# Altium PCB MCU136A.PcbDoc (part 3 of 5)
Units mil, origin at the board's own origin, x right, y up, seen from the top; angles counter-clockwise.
Board outline 3937.01 x 4724.41 mil, 4 copper layers (Top Layer, Signal Layer 1, Signal Layer 2, Bottom Layer), stack 60 mil thick; 390 components, 224 nets, 1130 pads, 1344 vias.
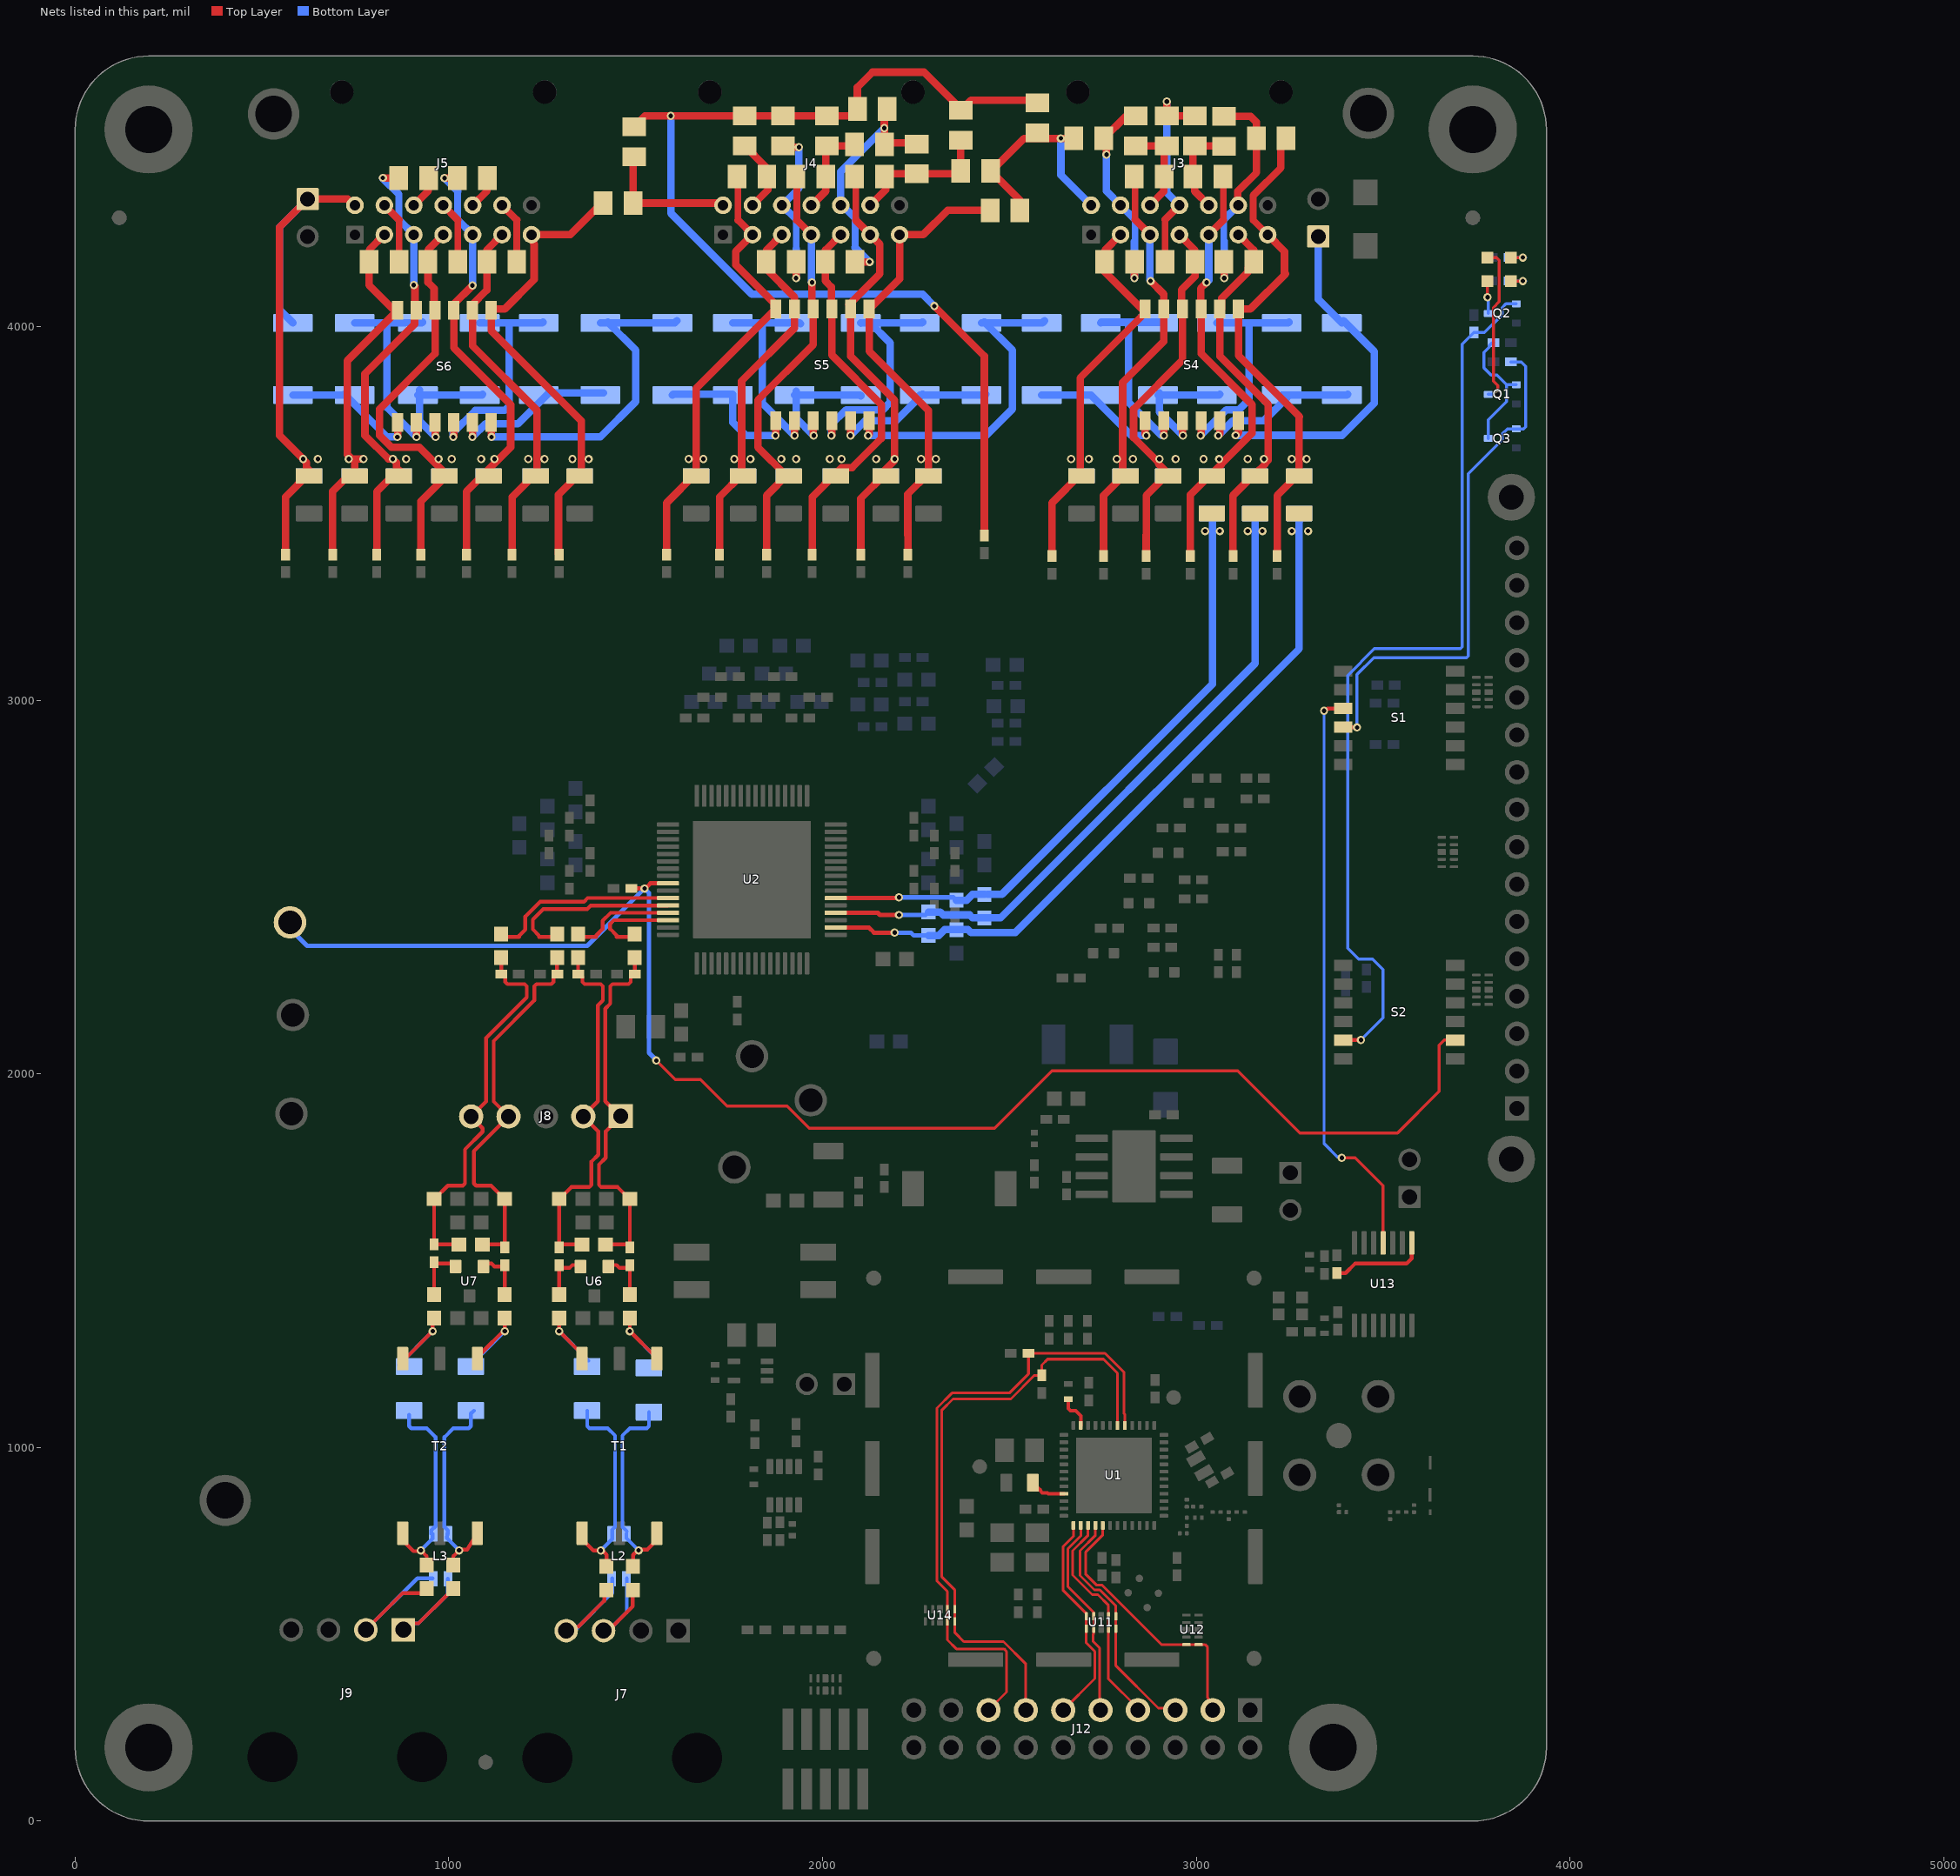
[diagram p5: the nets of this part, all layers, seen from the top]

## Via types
v1: diameter 22, hole 12, Top Layer to Bottom Layer, tented both sides, 890 vias
v2: diameter 22.01, hole 12.01, Top Layer to Bottom Layer, tented both sides, 402 vias
v3: diameter 19.68, hole 7.87, Top Layer to Bottom Layer, tented both sides, 21 vias
v4: diameter 24, hole 8, Top Layer to Bottom Layer, tented both sides, 12 vias
v5: diameter 20, hole 10, Top Layer to Bottom Layer, tented both sides, 7 vias
v6: diameter 24.8, hole 12.99, Top Layer to Bottom Layer, tented bottom, 6 vias
v7: diameter 17.46, hole 7.87, Top Layer to Bottom Layer, tented both sides, 6 vias

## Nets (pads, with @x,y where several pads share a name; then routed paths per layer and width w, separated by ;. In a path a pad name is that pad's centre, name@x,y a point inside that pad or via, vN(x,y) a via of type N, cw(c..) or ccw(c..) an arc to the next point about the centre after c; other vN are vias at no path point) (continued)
CB16: C21.2 C23.1 R34.2 R36.2 U2.6 | length 1683.6
  Top Layer w11.81: U2.6@2035.43,2470.47 2200,2470.47 2201.97,2472.44 v2(2204.72,2472.44) v2@2202.77,2470.49
  Bottom Layer w11.81: v2(2204.72,2472.44) 2350.39,2472.44 C23.1@2358.27,2464.57
  Bottom Layer w20: C23.1@2358.27,2464.57 2385.83,2464.57 2401.57,2480.31 C21.2@2433.07,2480.31 ; C21.2@2440.94,2480.31 2480.32,2480.31 3043.31,3043.31 R36.2@3043.31,3480.32
  other v2: 3023.62,3452.76 3062.99,3452.76
CB17: C19.2 C21.1 R31.2 R33.2 U2.4 | length 1813.8
  Top Layer w11.81: U2.4@2035.43,2431.1 2147.64,2431.1 2153.54,2425.2 v2(2204.72,2425.2)
  Bottom Layer w11.81: v2(2204.72,2425.2) 2275.59,2425.2 C19.2@2283.46,2433.07
  Bottom Layer w20: C19.2@2283.46,2433.07 2314.96,2433.07 2322.83,2425.2 2393.7,2425.2 2401.57,2417.32 C21.1@2433.07,2417.32 2476.38,2417.32 3157.81,3098.75 R33.2@3157.81,3495.67
  other v2: 3137.8,3452.76 3177.17,3452.76
CB18: C18.2 C19.1 R28.2 R30.2 U2.2 | length 1927.3
  Top Layer w11.81: U2.2@2035.43,2391.73 2124.02,2391.73 2137.8,2377.95 v2(2193.14,2377.95)
  Bottom Layer w11.81: v2(2193.14,2377.95) 2236.22,2377.95 2244.09,2370.08 C19.1@2283.46,2370.08
  Bottom Layer w20: C19.1@2283.46,2370.08 2311.02,2370.08 2326.77,2385.83 C18.2@2358.27,2385.83 2389.76,2385.83 2397.64,2377.95 2515.75,2377.95 3275.59,3137.8 3275.59,3480.32 R30.2@3283.46,3488.19
  other v2: 3255.91,3452.76 3299.21,3452.76
CC_EXT_IO: J12.3 U1.41 U12.1 U12.10 | length 730.9
  Top Layer w7: U1.41@2750,791.34 2750,765.75 2704.72,720.47 2704.72,659.79 2732.66,631.86 2747.43,631.86 2906.85,472.44 U12.10@2973.56,472.44 U12.1@3006.44,472.44 3023.62,472.44 3030.45,465.61 3030.45,418.37 3030.45,329.93 3033,327.38 3033,307.94 J12.3@3044.09,296.85
CC_I2C_SCL: J12.13 R157.1 U1.18 U14.5 U14.6 | length 1656.7
  Top Layer w7: J12.13@2544.09,296.85 2543.31,297.64 2543.31,421.51 2484.5,480.32 2377.95,480.32 2354.33,503.94 2354.33,534.18 2354.33,567.06 2354.33,618.11 2319.24,653.2 2319.24,1100.07 2349.09,1129.92 2503.94,1129.92 2566.93,1192.91 R157.1@2586.61,1192.91 2586.61,1220.47 2602.36,1236.22 2610.24,1236.22 2751.97,1236.22 2789.37,1198.82 U1.18@2789.37,1059.06
CC_I2C_SDA: J12.15 R156.1 U1.17 U14.4 U14.7 | length 1734.5
  Top Layer w7: U14.4@2333.85,534.18 2333.85,566.95 U14.7@2334.18,567.28 ; U14.4@2334.18,534.18 2334.18,484.71 2358.2,460.69 2469.74,460.69 2485.74,460.69 2492.45,453.99 2492.45,345.2 J12.15@2444.09,296.85 ; U14.7@2334.18,567.06 2334.18,614.63 2306.24,642.58 2306.24,1105.45 2346.46,1145.67 2500,1145.67 2551.18,1196.85 R156.1@2551.18,1248.03 ; R156.1@2551.18,1251.97 2755.91,1251.97 2807.09,1200.79 2807.09,1090.55 2809.06,1088.58 U1.17@2809.06,1059.06
CC_SPI_CS: J12.11 U1.37 U11.1 U11.10 | length 576.3
  Top Layer w7: J12.11@2644.09,296.85 2728.45,381.2 2728.45,453.99 2705.85,476.59 2705.85,515.06 2705.85,547.93 2705.85,555.56 2643.29,618.11 2643.29,733.99 2671.26,761.96 U1.37@2671.26,791.34
CC_SPI_MISO: J12.7 U1.39 U11.4 U11.7 | length 585.3
  Top Layer w7: U1.39@2710.63,791.34 2710.63,764.56 2669.29,723.22 2669.29,658.46 2721.89,605.86 2736.66,605.86 2765.34,577.18 U11.7@2765.34,547.93 ; U11.4@2764.9,515.06 U11.7@2764.9,547.5 ; U11.4@2765.34,515.06 2765.34,380.33 J12.7@2842.52,303.15
CC_SPI_MOSI: J12.9 U1.38 U11.2 U11.9 | length 546.6
  Top Layer w7: U1.38@2690.94,791.34 2690.94,763.26 2656.29,728.61 2656.29,627.17 2725.53,557.93 2725.53,547.93 2725.97,547.5 2725.97,515.5 2725.53,515.06 2725.53,500.9 2724.34,499.7 2724.34,480.39 2741.45,463.28 2741.45,299.5 J12.9@2744.09,296.85
CC_SPI_SCK: J12.5 U1.40 U11.5 U11.6 | length 649.5
  Top Layer w7: U1.40@2730.32,791.34 2730.32,764.56 2688.98,723.22 2688.98,657.16 2727.27,618.86 2742.04,618.86 2785.02,575.88 U11.6@2785.02,547.93 U11.5@2785.02,515.06 2785.02,415.76 2898.78,302.01 2938.94,302.01 J12.5@2944.09,296.85
CELL0: J5.2 J6.1 R106.1 R107.1 R108.1 R176.1 | length 1574.7
  Top Layer w20: R107.1@562.99,3385.83 R107.1@562.99,3389.76 562.99,3544.09 R106.1@625.98,3607.09 ; R106.1@649.61,3606.3 635.74,3606.3 619.37,3622.68 619.37,3636 610.24,3645.13 v2(610.24,3645.67) 547.24,3708.66 547.24,4266.54 J6.1@622.05,4341.34 729.53,4341.34 J5.2@748.03,4322.83
  Bottom Layer w20: R176.1@582.68,4009.84 547.24,4045.28 547.24,4266.54 J6.1@622.05,4341.34
  other v2: 649.61,3645.67
CELL1: J5.3 R101.1 R103.1 R104.1 R111.2 S6.12 | length 1007.2
  Top Layer w20: R103.1@688.98,3389.76 688.98,3559.06 721.42,3591.5 721.61,3591.5 728.53,3598.41 R101.1@728.53,3598.61 ; R101.1@748.03,3607.09 748.03,3645.67 ; v2(771.65,3645.67) 748.03,3645.67 ; R111.2@786.77,4173.23 786.77,4110.87 S6.12@858.27,4039.37 ; R111.2@787.4,4173.23 787.4,4205.94 J5.3@827.52,4246.06 ; S6.12@863.19,4043.7 728.35,3908.86 728.35,3657.39 740.06,3645.67 748.03,3645.67
  other v1: 732.28,3645.67
CELL1_Lad: R175.1 R176.2 S6.1 | length 366.2
  Top Layer w20: v1(862.2,3704.72) 863.19,3705.71 S6.1@863.19,3743.7
  Bottom Layer w20: R176.2@582.68,3816.93 R175.1@720.47,3816.93 ; R175.1@720.47,3818.9 834.65,3704.72 v1(862.2,3704.72)
CELL2: J5.5 R97.1 R98.1 R99.1 R110.2 S6.11 | length 1216.4
  Top Layer w10: v1(823.59,4398.26) v1@824.2,4397.64
  Top Layer w20: R98.1@807.09,3389.76 807.09,3558.36 839.72,3591 839.72,3591.5 855.32,3607.09 R97.1@866.14,3607.09 ; v1@824.2,4397.64 R110.2@865.51,4397.64 ; R97.1@871.65,3612.6 869.6,3612.6 859.52,3622.68 859.52,3636 850.39,3645.13 v2(850.39,3645.67) 850.01,3646.05 838.2,3646.05 775.59,3708.66 775.59,3874.02 908.19,4006.61 908.19,4038.7 S6.11@913.19,4043.7 ; v1(906.13,4111.17) 909.45,4107.85 S6.11@909.45,4043.7
  Bottom Layer w18: 866.14,4286.18 866.14,4354.33
  Bottom Layer w20: v1@822.83,4397.64 866.14,4354.33 ; 866.14,4286.18 J5.5@906.26,4246.06 v1@906.26,4110.98
  other v2: 885.83,3645.67
CELL2_Lad: R174.1 R175.2 S6.2 | length 556.7
  Top Layer w20: S6.2@913.19,3743.7 913.19,3704.92 v1(913.39,3704.72)
  Bottom Layer w20: R175.2@748.03,4009.84 R174.1@917.32,4009.84 927.16,4009.84 R174.1@929.13,4011.81 ; 834.65,4007.87 834.65,3783.46 v1(913.39,3704.72)
CELL2_NEG: J5.4 R111.1 | length 167.8
  Top Layer w18: R111.1@866.77,4173.23 866.77,4285.55
  Top Layer w20: J5.4@827.52,4324.8 866.77,4285.55
CELL3: J5.7 R94.1 R95.1 R96.1 R109.2 S6.10 | length 1099
  Top Layer w20: R95.1@925.2,3385.83 925.2,3532.28 989.76,3596.85 995.67,3602.76 921.26,3677.17 846.46,3677.17 814.96,3708.66 814.96,3779.53 963.19,3927.76 S6.10@963.19,4043.7 ; R109.2@944.25,4173.23 944.25,4118.74 960.63,4102.36 S6.10@960.63,4043.7 ; R109.2@944.88,4173.23 944.88,4205.94 J5.7@985,4246.06 ; R94.1@983.86,3602.76 R94.1@988.19,3607.09
  other v2: 972.44,3645.67 1007.87,3645.67
CELL3_Lad: R173.1 R174.2 S6.3 | length 357.5
  Top Layer w20: S6.3@963.19,3743.7 963.19,3706.1 v1(964.57,3704.72)
  Bottom Layer w20: R174.2@917.32,3816.93 1088.58,3816.93 R173.1@1090.55,3818.9 ; R174.2@921.26,3830.71 921.26,3748.03 v1(964.57,3704.72)
CELL3_NEG: J5.6 R110.1 | length 100.6
  Top Layer w20: J5.6@906.26,4324.8 944.88,4363.43 R110.1@944.88,4409.45
CELL4: J5.9 R91.1 R92.1 R93.1 R105.2 S6.9 | length 1203.5
  Top Layer w20: v1(988.19,4397.64) R105.2@1019.68,4397.64 ; S6.9@1011.81,4043.7 1011.81,4058.72 v1(1063.37,4110.28) ; S6.9@1013.19,4043.7 1013.19,3943.5 1165.35,3791.34 1165.35,3677.17 R93.1@1100.79,3612.6 ; R92.1@1047.24,3393.7 1047.24,3558.86 1079.88,3591.5 1095.47,3607.09 R93.1@1106.3,3607.09
  Bottom Layer w10: v1@1062.99,4110.24 v1@1063.74,4110.98
  Bottom Layer w18: 1023.62,4286.18 1023.62,4362.2
  Bottom Layer w20: v1(988.19,4397.64) 1023.62,4362.2 ; 1023.62,4286.18 J5.9@1063.74,4246.06 v1@1063.74,4110.98
  other v1: 1122.05,3645.67
  other v2: 1086.61,3645.67
CELL4_Lad: R172.1 R173.2 S6.4 | length 617
  Top Layer w20: v1(1011.81,3704.72) 1013.19,3706.1 S6.4@1013.19,3743.7
  Bottom Layer w20: v1(1011.81,3704.72) 1011.81,3716.54 1070.87,3775.59 1149.7,3775.59 1161.42,3787.31 1161.42,4003.94 ; R173.2@1082.68,4009.84 R172.1@1240.16,4009.84 1250,4009.84 R172.1@1251.97,4011.81
CELL4_NEG: J5.8 R109.1 | length 167.8
  Top Layer w18: R109.1@1024.25,4173.23 1024.25,4285.55
  Top Layer w20: J5.8@985,4324.8 1024.25,4285.55
CELL5: J5.11 R86.1 R88.1 R89.1 R102.2 S6.8 | length 964.9
  Top Layer w20: S6.8@1062.99,4059.06 1101.73,4097.8 R102.2@1101.73,4173.23 ; S6.8@1063.19,4043.7 1063.19,3948.62 1236,3775.81 1236,3610.8 1169.29,3544.09 R88.1@1169.29,3397.64 ; R102.2@1102.36,4173.23 1102.36,4205.94 J5.11@1142.48,4246.06
  other v1: 1255.91,3645.67
  other v2: 1212.6,3645.67
CELL5_Lad: R171.1 R172.2 S6.5 | length 438.4
  Top Layer w20: v1(1062.99,3704.72) 1063.19,3704.92 S6.5@1063.19,3743.7
  Bottom Layer w20: v1(1062.99,3704.72) 1098.43,3740.16 1185.04,3740.16 1267.72,3822.83 R171.1@1413.39,3822.83
CELL5_NEG: J5.10 R105.1 | length 92.8
  Top Layer w20: J5.10@1063.74,4324.8 1102.36,4363.43 R105.1@1102.36,4401.57
CELL6: J5.13 R81.1 R82.1 R83.1 R100.2 S6.7 | length 1278.2
  Top Layer w20: S6.7@1113.19,4043.7 1113.19,3989.17 1354.33,3748.03 ; S6.7@1114.17,4047.24 1149.61,4047.24 1228.35,4125.98 1228.35,4220.73 1226.43,4222.64 1226.43,4240.85 J5.13@1221.22,4246.06 1324.8,4246.06 R100.2@1413.39,4334.65 ; R82.1@1295.28,3389.76 1293.46,3391.57 1293.46,3550.16 1354.74,3611.43 1354.74,3747.63
  other v1: 1374.14,3645.37
  other v2: 1330.71,3645.67
CELL6_Lad: R170.1 R171.2 S6.6 | length 915.1
  Top Layer w20: S6.6@1113.19,3743.7 1113.19,3705.71 v1(1114.17,3704.72)
  Bottom Layer w20: v1(1114.17,3704.72) 1405.51,3704.72 1500,3799.21 1500,3937.01 R171.2@1425.2,4011.81 ; R171.2@1405.51,4009.84 R170.1@1598.43,4009.84 1604.33,4009.84 R170.1@1610.24,4015.75
CELL6_NEG: J5.12 R102.1 | length 167.8
  Top Layer w18: R102.1@1181.73,4173.23 1181.73,4285.55
  Top Layer w20: J5.12@1142.48,4324.8 1181.73,4285.55
CELL7: J4.3 R74.1 R77.1 R78.1 R90.2 S5.12 | length 1212.9
  Top Layer w18: R90.2@1771.02,4401.57 1773.9,4398.7 1773.9,4285.16
  Top Layer w20: R77.1@1582.68,3389.76 1582.68,3528.35 1661.42,3607.09 1661.42,3834.06 S5.12@1875,4047.64 1870,4052.64 1870,4063.07 1767.72,4165.35 1767.72,4201.26 J4.3@1812.52,4246.06 ; 1773.9,4285.16 J4.3@1812.76,4246.3
  other v1: 1681.1,3645.67
  other v2: 1641.73,3645.67
CELL7_Lad: R169.1 R170.2 S5.1 | length 403.3
  Top Layer w20: v1(1874.02,3708.66) 1875,3709.65 S5.1@1875,3747.64
  Bottom Layer w20: R170.2@1598.43,3816.93 1600.39,3818.9 R169.1@1759.84,3818.9 ; R169.1@1759.84,3816.93 1759.84,3744.09 1795.28,3708.66 v1(1874.02,3708.66)
CELL7_NEG: J4.2 R100.1 R118.2 | length 371.3
  Top Layer w20: R118.2@1492.13,4456.69 1492.76,4456.06 R100.1@1492.76,4330.71 1732.28,4330.71 J4.2@1736.22,4326.77
CELL8: J4.5 R69.1 R70.1 R71.1 R87.2 S5.11 | length 984.3
  Top Layer w20: R70.1@1724.41,3397.64 1724.41,3544.09 R69.1@1785.04,3604.72 ; R69.1@1787.4,3607.09 R69.1@1785.04,3604.72 ; R87.2@1849.76,4173.23 1849.76,4154.17 1925.2,4078.74 S5.11@1925.2,4047.64 ; R87.2@1850.39,4173.23 1850.39,4205.2 J4.5@1891.26,4246.06 ; S5.11@1925,4047.64 1925,3995.87 1783.46,3854.33 1783.46,3606.3 R69.1@1785.04,3604.72
  other v1: 1763.78,3645.67
  other v2: 1807.09,3645.67
CELL8_Lad: R168.1 R169.2 S5.2 | length 552.1
  Top Layer w20: S5.2@1925,3747.64 1925,3708.86 v1(1925.2,3708.66)
  Bottom Layer w20: R169.2@1759.84,4009.84 R168.1@1925.2,4009.84 1938.98,4009.84 R168.1@1940.94,4007.87 ; 1838.58,4003.94 1838.58,3795.28 v1(1925.2,3708.66)
CELL8_NEG: J4.4 R90.1 R117.2 | length 207.1
  Top Layer w20: R117.2@1787.4,4488.19 1851.02,4424.57 R90.1@1851.02,4401.57 ; J4.4@1812.52,4324.8 1854.33,4366.61 R90.1@1854.33,4401.57
CELL9: J4.7 R65.1 R67.1 R68.1 R85.2 S5.10 | length 1146.8
  Top Layer w18: R85.2@1928.5,4401.57 1931.38,4398.7 1931.38,4285.16
  Top Layer w20: R67.1@1850.39,3389.76 1850.39,3548.03 R65.1@1909.45,3607.09 ; R65.1@1905.51,3598.43 1903.15,3600.79 1826.77,3677.17 1826.77,3803.15 1975,3951.38 S5.10@1975,4047.64 ; 1931.38,4285.16 J4.7@1968.5,4248.03 ; S5.10@1971.86,4055.7 v1(1971.86,4118.44)
  Bottom Layer w20: J4.7@1970,4246.06 1970,4120.55 v1@1972.44,4118.11
  other v2: 1889.76,3645.67 1929.13,3645.67
CELL9_Lad: R167.1 R168.2 S5.3 | length 355.2
  Top Layer w20: S5.3@1975,3747.64 1975,3710.04 v1(1976.38,3708.66)
  Bottom Layer w20: R168.2@1925.2,3816.93 2100.39,3816.93 R167.1@2102.36,3814.96 ; R168.2@1929.13,3826.77 1929.13,3755.91 v1(1976.38,3708.66)
CELL9_NEG: J4.6 R87.1 R116.2 | length 476.5
  Top Layer w20: R116.2@1889.76,4480.32 v1(1937.01,4480.32) ; v1(1929.13,4129.92) 1929.45,4130.24 1929.45,4172.91 R87.1@1929.76,4173.23
  Bottom Layer w18: 1929.13,4208.66 1929.88,4209.41 1929.88,4286.18
  Bottom Layer w20: v1(1929.13,4129.92) 1929.13,4208.66 ; 1929.88,4286.18 J4.6@1891.26,4324.8 1891.5,4325.04 1937.01,4370.55 v1(1937.01,4480.32)
CELL10: J4.9 R62.1 R63.1 R64.1 R80.2 S5.9 | length 1020.7
  Top Layer w20: R63.1@1972.44,3389.76 1972.44,3544.09 2035.43,3607.09 2051.02,3622.68 2079.37,3622.68 2157.48,3700.79 2157.48,3791.34 2025,3923.82 S5.9@2025,4047.64 ; R80.2@2007.24,4173.23 2007.24,4122.68 2023.62,4106.3 S5.9@2023.62,4055.12 ; R80.2@2007.87,4173.23 2007.87,4205.2 J4.9@2048.74,4246.06
  other v2: 2019.68,3645.67 2051.18,3645.67
CELL10_Lad: R166.1 R167.2 S5.4 | length 658.5
  Top Layer w20: v1(2023.62,3708.66) 2025,3710.04 S5.4@2025,3747.64
  Bottom Layer w10: R167.2@2102.36,4003.94 R167.2@2105.31,4006.89
  Bottom Layer w20: v1(2023.62,3708.66) 2023.62,3737.94 2062.99,3777.31 2161.03,3777.31 2181.1,3797.38 2181.1,3956.69 R167.2@2125.98,4011.81 ; R167.2@2102.36,4009.84 R166.1@2259.84,4009.84 2265.75,4009.84 R166.1@2267.72,4011.81
CELL10_NEG: J4.8 R84.2 R85.1 R115.2 | length 250.8
  Top Layer w20: J4.8@1972.44,4326.77 2008.5,4362.83 R85.1@2008.5,4401.57 R115.2@2008.5,4483.62 ; R115.2@2011.81,4483.62 2089.92,4483.62 R84.2@2090.55,4484.25
CELL11: J4.11 R55.1 R58.1 R59.1 R76.2 S5.8 | length 1144.7
  Top Layer w18: R76.2@2085.98,4401.57 2088.86,4398.7 2088.86,4284.68
  Top Layer w20: S5.8@2070.87,4059.06 2152.98,4141.17 2152.98,4220.56 J4.11@2127.48,4246.06 2088.86,4284.68 ; S5.8@2075,4047.64 2075,3921.06 2192.91,3803.15 2192.91,3641.73 R55.1@2161.42,3610.24 ; R58.1@2102.36,3393.7 2102.36,3540.16 R55.1@2169.29,3607.09
  other v1: 2192.91,3645.67
  other v2: 2143.55,3645.67
CELL11_Lad: R165.1 R166.2 S5.5 | length 455.6
  Top Layer w20: v1(2074.8,3708.66) 2075,3708.86 S5.5@2075,3747.64
  Bottom Layer w20: v1(2074.8,3708.66) 2114.17,3748.03 2196.85,3748.03 R166.2@2267.72,3818.9 ; R166.2@2259.84,3816.93 R165.1@2425.2,3816.93 2435.04,3816.93 R165.1@2437.01,3818.9
CELL11_NEG: J4.10 R79.2 R80.1 R84.1 R114.2 | length 668.6
  Top Layer w20: R80.1@2087.24,4173.23 v1(2125.98,4173.23) ; R114.2@2165.35,4582.68 v1(2165.35,4531.5) 2165.98,4530.87 R84.1@2165.98,4488.19 2169.92,4492.13 R79.2@2259.84,4492.13
  Bottom Layer w18: 2087.24,4211.97 2087.24,4229.95 2087.36,4230.07 2087.36,4262.06 2087.24,4262.18 2087.24,4290.71
  Bottom Layer w20: J4.10@2048.74,4324.8 2048.74,4414.88 v1(2165.35,4531.5) ; J4.10@2051.18,4326.77 2087.24,4290.71 ; 2087.24,4211.97 v1(2125.98,4173.23)
CELL12: J4.13 R50.1 R51.1 R52.1 R73.2 S5.7 | length 1244.3
  Top Layer w20: S5.7@2125,4047.64 2125,3934.06 2283.46,3775.59 R50.1@2283.46,3606.3 ; S5.7@2125.98,4047.24 2206.22,4127.48 J4.13@2206.22,4246.06 2269.68,4246.06 2334.65,4311.02 R73.2@2448.19,4311.02 ; R51.1@2228.35,3393.7 2228.35,3441.69 2228.09,3441.94 2228.09,3551.72 R50.1@2283.46,3607.09
  other v2: 2263.78,3645.67 2303.15,3645.67
CELL12_Lad: R164.1 R165.2 S5.6 | length 890.4
  Top Layer w20: v1(2122.05,3708.66) 2125,3711.61 S5.6@2125,3747.64
  Bottom Layer w20: v1(2122.05,3708.66) 2437.01,3708.66 2507.87,3779.53 2507.87,3937.01 R165.2@2433.07,4011.81 ; R165.2@2425.2,4009.84 R164.1@2586.6,4009.84 2588.58,4009.84 R164.1@2594.49,4015.75
CELL12_NEG: J4.12 R75.2 R76.1 R79.1 R113.2 | length 370.4
  Top Layer w20: J4.12@2127.48,4324.8 2169.29,4366.61 R76.1@2169.29,4401.57 ; R76.1@2165.98,4401.57 2173.23,4408.82 R79.1@2251.97,4408.82 R75.2@2357.64,4408.82 ; R75.2@2369.45,4417.32 2369.45,4498.1 R113.2@2370.08,4498.73
CELL13: J3.3 R43.1 R46.1 R47.1 R61.2 S4.12 | length 1027
  Top Layer w20: R46.1@2614.17,3389.76 2614.17,3528.35 2692.91,3607.09 2689.35,3610.65 2689.35,3862.58 2858.19,4031.42 2858.19,4042.64 S4.12@2863.19,4047.64 ; R61.2@2755.28,4173.23 2755.28,4146.3 S4.12@2858.56,4043.01 ; R61.2@2755.91,4173.23 2755.91,4204.45 J3.3@2797.52,4246.06
  other v2: 2665.35,3645.67 2712.6,3645.67
CELL13_Lad: R163.1 R164.2 S4.1 | length 364.6
  Top Layer w20: S4.1@2863.19,3747.64 2863.19,3711.61 v1(2866.14,3708.66)
  Bottom Layer w20: R164.2@2586.6,3816.93 2718.5,3816.93 2826.77,3708.66 v1(2866.14,3708.66)
CELL13_NEG: J3.2 R72.2 R73.1 R75.1 R112.2 | length 607.7
  Top Layer w20: R75.1@2449.45,4417.32 2527.56,4339.21 R73.1@2527.56,4307.09 ; R75.1@2452.76,4417.32 2539.37,4503.94 v1(2637.8,4503.94) R72.2@2669.29,4503.94
  Bottom Layer w20: v1(2637.8,4503.94) 2637.8,4405.79 J3.2@2718.78,4324.8
CELL14: J3.5 R40.1 R41.1 R42.1 R57.1 S4.11 | length 1121.9
  Top Layer w18: R57.1@2834.02,4401.57 2836.14,4399.45 2836.14,4286.18
  Top Layer w20: R41.1@2751.97,3385.83 2751.97,3548.03 2811.02,3607.09 2803.15,3614.96 2803.15,3850.5 2913.19,3960.54 S4.11@2913.19,4047.64 ; 2836.14,4286.18 J3.5@2876.26,4246.06 ; v1(2877.95,4122.05) 2913.39,4086.61 S4.11@2913.39,4047.64
  Bottom Layer w20: J3.5@2876.26,4246.06 2876.26,4123.74 v1(2877.95,4122.05)
  other v2: 2787.4,3645.67 2830.71,3645.67
CELL14_Lad: R162.1 R163.2 S4.2 | length 539.1
  Top Layer w20: S4.2@2913.19,3747.64 2913.19,3708.86 v1(2913.39,3708.66)
  Bottom Layer w20: R163.2@2744.09,4009.84 2746.06,4011.81 R162.1@2905.51,4011.81 ; 2818.9,4003.94 2818.9,3797.38 2907.61,3708.66 v1(2913.39,3708.66)
CELL14_NEG: J3.4 R60.2 R61.1 R72.1 | length 528.5
  Top Layer w20: R72.1@2752.6,4503.94 2811.65,4562.99 R60.2@2842.52,4562.99 ; v1(2759.84,4460.63) R72.1@2759.84,4484.25 ; v1(2834.65,4129.92) R61.1@2834.65,4157.48
  Bottom Layer w18: 2834.65,4227.07 2836.14,4228.57 2836.14,4286.18
  Bottom Layer w20: v1(2759.84,4460.63) 2759.84,4362.48 J3.4@2797.52,4324.8 2836.14,4286.18 ; v1(2834.65,4129.92) 2834.65,4227.07
CELL15: J3.7 R37.1 R38.1 R39.1 R54.1 S4.10 | length 1014
  Top Layer w20: R38.1@2866.14,3385.83 2866.14,3441.69 2866.39,3441.94 2866.39,3548.28 R37.1@2925.2,3607.09 ; R37.1@2929.13,3606.3 2925.39,3606.3 2898.78,3632.91 2898.78,3636.65 2832.19,3703.24 2832.19,3779.27 2963.19,3910.27 S4.10@2963.19,4047.64 ; J3.7@2955,4246.06 2996.06,4205 R54.1@2996.06,4173.23 ; S4.10@2960.63,4047.64 2960.63,4098.43 2996.69,4134.49 R54.1@2996.69,4173.23
  other v1: 2901.57,3645.67
  other v2: 2944.88,3645.67
CELL15_Lad: R161.1 R162.2 S4.3 | length 346
  Top Layer w20: S4.3@2963.19,3747.64 2963.19,3710.04 v1(2964.57,3708.66)
  Bottom Layer w20: R162.2@2897.64,3816.93 R161.1@3055.12,3816.93 3061.02,3816.93 R161.1@3062.99,3818.9 ; R162.2@2901.57,3822.83 2901.57,3771.65 v1(2964.57,3708.66)
CELL15_NEG: J3.6 R56.2 R57.2 R60.1 | length 259.9
  Top Layer w20: R60.1@2838.58,4483.62 R56.2@2916.69,4483.62 ; J3.6@2876.26,4324.8 2913.39,4361.93 R57.2@2913.39,4401.57 ; R57.2@2914.02,4401.57 2914.02,4480.94 R56.2@2916.69,4483.62 ; R56.2@2921.26,4488.19 R56.2@2916.69,4483.62
CELL16: J3.9 R34.1 R35.1 R36.1 R49.1 S4.9 | length 1168.8
  Top Layer w18: R49.1@3070.87,4405.51 3072.36,4404.02 3072.36,4284.96
  Top Layer w20: R35.1@2984.25,3385.83 2984.25,3549.58 3041.76,3607.09 3043.63,3607.09 3068.17,3631.63 3068.17,3633.5 3149.61,3714.94 3149.61,3791.34 3013.19,3927.76 S4.9@3013.19,4047.64 ; S4.9@3011.81,4047.64 3011.81,4102.36 v1(3027.56,4118.11) ; J3.9@3035.43,4248.03 3072.36,4284.96
  Bottom Layer w20: v1(3027.56,4118.11) 3033.74,4124.29 J3.9@3033.74,4246.06
  other v1: 3061.48,3645.27
  other v2: 3019.68,3645.67
CELL16_Lad: R160.1 R161.2 S4.4 | length 601.9
  Top Layer w20: v1(3011.81,3708.66) 3013.19,3710.04 S4.4@3013.19,3747.64
  Bottom Layer w20: v1(3011.81,3708.66) 3080.46,3777.31 3113.79,3777.31 3141.73,3805.25 3141.73,4003.94 ; R161.2@3055.12,4009.84 R160.1@3228.35,4009.84 3246.06,4009.84 R160.1@3248.03,4011.81
CELL16_NEG: J3.8 R53.2 R54.2 R56.1 | length 577
  Top Layer w18: R54.2@2916.69,4173.23 2916.69,4229.75 2916.38,4230.07 2916.38,4262.06 2916.69,4262.38 2916.69,4286.5
  Top Layer w20: 2916.69,4286.5 J3.8@2955,4324.8 ; v1(2921.26,4602.36) R56.1@2921.26,4563.62 2999.37,4563.62 R53.2@3000,4562.99
  Bottom Layer w20: v1(2921.26,4602.36) 2921.26,4358.54 J3.8@2955,4324.8
CELL17: J3.11 R31.1 R32.1 R33.1 R45.1 S4.8 | length 1003.1
  Top Layer w20: S4.8@3063.19,4047.64 3063.19,3921.06 3192.91,3791.34 3192.91,3642.52 3183.9,3633.5 3183.9,3631.33 3159.65,3607.09 3157.48,3607.09 3098.43,3548.03 R32.1@3098.43,3385.83 ; S4.8@3068.19,4047.64 3068.19,4076.06 3139.17,4147.05 3139.17,4158.23 R45.1@3154.17,4173.23 ; J3.11@3112.48,4246.06 3153.54,4205 R45.1@3153.54,4177.17
  other v1: 3181.1,3645.67
  other v2: 3137.8,3645.67
CELL17_Lad: R159.1 R160.2 S4.5 | length 446.1
  Top Layer w20: v1(3059.06,3708.66) 3063.19,3712.8 S4.5@3063.19,3747.64
  Bottom Layer w20: v1(3059.06,3708.66) 3098.43,3748.03 3181.1,3748.03 R160.2@3244.09,3811.02 ; R160.2@3228.35,3816.93 3403.54,3816.93 R159.1@3405.51,3818.9
CELL17_NEG: J3.10 R48.2 R49.2 R53.1 | length 258.3
  Top Layer w20: R49.2@2991.5,4401.57 2991.5,4483.62 R53.1@2992.13,4484.25 ; R49.2@2996.06,4401.57 2996.06,4362.48 J3.10@3033.74,4324.8 ; R53.1@2996.06,4483.62 3078.11,4483.62 R48.2@3078.74,4484.25
CELL18: J3.13 R28.1 R29.1 R30.1 R44.1 S4.7 | length 1348.8
  Top Layer w18: 3152.6,4351.14 3152.6,4284.68 J3.13@3191.22,4246.06
  Top Layer w20: S4.7@3113.19,4047.64 3113.19,3922.24 3276.55,3758.88 ; S4.7@3114.17,4047.24 3145.04,4047.24 3239.53,4141.73 ; 3152.6,4351.14 3226.65,4425.2 3226.65,4489.8 R44.1@3240.79,4503.94 ; J3.13@3191.22,4246.06 3236.22,4201.06 3236.22,4141.73 ; R29.1@3216.54,3389.76 3216.54,3548.03 3275.59,3607.09 3275.59,3759.79
  other v2: 3255.91,3645.67 3295.28,3645.67
CELL18_Lad: J2.1 R159.2 S4.6 | length 960.4
  Top Layer w20: v1(3105.6,3709.11) 3113.19,3716.7 S4.6@3113.19,3747.64
  Bottom Layer w20: v1(3105.6,3709.11) 3390.22,3709.11 3476.38,3795.28 3476.38,3933.07 R159.2@3393.7,4015.75 ; J2.1@3326.77,4241.34 3326.77,4072.83 R159.2@3389.76,4009.84
CELL18_NEG: J3.12 R44.2 R45.2 R48.1 | length 591.3
  Top Layer w20: R48.1@3070.87,4562.99 R48.1@3074.8,4562.99 3145.67,4562.99 3160.79,4547.87 R44.2@3160.79,4503.94 ; v1(3074.8,4129.92) R45.2@3074.8,4169.29 ; J3.12@3112.48,4324.8 3111.08,4326.2 3111.08,4362.03 3161.42,4412.37 R44.2@3161.42,4503.94
  Bottom Layer w18: 3073.86,4286.18 3073.86,4229.12 3074.8,4228.18
  Bottom Layer w20: 3073.86,4286.18 J3.12@3112.48,4324.8 ; v1(3074.8,4129.92) 3074.8,4228.18
CELL_BB: R66.2 R112.1 R113.1 R114.1 R115.1 R116.1 R117.1 R118.1 | length 2969.1
  Top Layer w20: R118.1@1496.06,4535.43 1524.25,4563.62 R117.1@1791.34,4563.62 R116.1@1893.7,4563.62 R115.1@2011.81,4563.62 2071.5,4563.62 R114.1@2091.88,4584.01 ; R114.1@2093.21,4582.68 2093.21,4640.46 2133.86,4681.1 2271.65,4681.1 R113.1@2370.08,4582.68 ; v1(2299.21,4055.12) 2433.07,3921.26 R66.2@2433.07,3440.94 ; R113.1@2370.08,4578.73 2397.65,4606.3 R112.1@2582.68,4606.3
  Bottom Layer w20: v1@1594.49,4562.99 1594.49,4303.15 1811.02,4086.61 2267.72,4086.61 v1(2299.21,4055.12)
  other v1: 1593.74,4564.12
COMH_ISO_N: J7.4 L2.4 R129.2 | length 335.4
  Top Layer w10: J7.4@1314.96,511.81 1322.83,519.68 1346.46,519.68 1416.05,589.28 1416.05,612.91 R129.2@1421.26,618.11
  Bottom Layer w10: J7.4@1343.79,517.02 1437.01,610.24 L2.4@1437.01,649.61
COMH_ISO_P: J7.3 L2.3 R122.2 | length 305.5
  Top Layer w10: J7.3@1413.39,511.81 1429.13,511.81 1492.13,574.8 R122.2@1492.13,618.11
  Bottom Layer w10: J7.3@1429.13,511.81 1476.38,559.06 L2.3@1476.38,649.61
COMH_N: R126.1 U2.45 | length 278.5
  Top Layer w10: R126.1@1346.46,2366.14 1394.12,2366.14 ; 1394.12,2370.08 1411.68,2387.64 1411.68,2409.86 1432.92,2431.1 U2.45@1586.61,2431.1
COMH_P: R119.1 U2.46 | length 244.4
  Top Layer w10: 1448.82,2366.14 R119.1@1496.06,2366.14 ; 1448.82,2370.5 1431.68,2387.64 1431.68,2401.57 1441.21,2411.1 1586.3,2411.1 U2.46@1586.61,2411.42
COMH_R1_N: C75.2 J8.2 R124.1 R125.1 R126.2 R127.1 | length 1001.9
  Top Layer w10: R127.1@1295.28,1535.43 1303.15,1543.31 R124.1@1354.33,1543.31 ; R127.1@1295.28,1543.31 R125.1@1295.28,1665.35 ; R125.1@1296.26,1665.35 1327.76,1696.85 1375.72,1696.85 1381.57,1702.71 1381.57,1765.2 1399.84,1783.46 1399.84,1845.83 J8.2@1359.84,1885.83 ; R126.2@1345.72,2318.9 R126.2@1345.72,2311.02 1345.72,2267.78 C75.2@1346.88,2266.62 1350.81,2266.62 1357.63,2259.81 1357.63,2246.02 1363.48,2240.16 1406.34,2240.16 1412.2,2234.3 1412.2,2196.39 1398.71,2182.9 1398.71,1926.47 J8.2@1358.71,1886.47
COMH_R1_P: C72.1 J8.1 R119.2 R120.1 R123.2 R124.2 | length 993.4
  Top Layer w10: R124.2@1418.97,1543.34 R120.1@1484.25,1543.34 ; J8.1@1458.71,1886.47 1418.71,1926.47 1418.71,2174.61 1432.2,2188.11 1432.2,2234.3 1438.06,2240.16 1480.92,2240.16 1486.78,2246.02 1486.78,2259.81 1493.59,2266.62 C72.1@1497.53,2266.62 ; J8.1@1459.84,1885.83 1419.84,1845.83 1419.84,1775.18 1401.57,1756.91 1401.57,1702.71 1407.43,1696.85 1451.77,1696.85 R123.2@1483.27,1665.35 ; R123.2@1484.25,1665.35 R120.1@1484.25,1543.34 ; R120.1@1488.19,1543.31 1488.15,1543.34 R120.1@1484.25,1543.34 ; C72.1@1497.64,2270.07 R119.2@1497.64,2311.02
COMH_R2_N: R127.2 R128.1 U6.2 | length 129.2
  Top Layer w10: R128.1@1295.28,1409.45 1295.28,1480.32 1322.83,1480.32 1330.71,1488.19 U6.2@1350.39,1488.19
COMH_R2_P: R120.2 R121.1 U6.1 | length 129.2
  Top Layer w10: U6.1@1429.13,1488.19 1448.82,1488.19 1456.69,1480.32 1484.25,1480.32 R121.1@1484.25,1409.45
COMHC_N: C76.2 L2.1 R129.1 T1.4 | length 600.2
  Top Layer w10: T1.4@1349.55,795.28 1349.55,761.49 1386.96,724.09 v1(1406.64,724.09) ; v1@1412.87,721.79 1422.39,712.28 R129.1@1422.39,680.78
  Bottom Layer w10: C76.2@1370.08,1098.43 1370.08,1057.04 1375.94,1051.18 1425.2,1051.18 1444.72,1031.65 1444.72,906.39 ; v1(1406.64,724.09) 1437.01,754.46 L2.1@1437.01,767.72 ; L2.1@1437.01,768.7 1437.01,779.56 1444.69,787.24 1444.69,906.36
COMHC_P: C71.2 L2.2 R122.1 T1.6 | length 596.1
  Top Layer w10: R122.1@1493.25,680.78 1493.25,712.28 1505.39,724.41 v1(1507.87,724.41) 1510.17,726.71 1531.31,726.71 1566.09,761.49 T1.6@1566.09,795.28
  Bottom Layer w10: 1464.69,898.07 1464.69,787.24 L2.2@1476.38,775.56 ; 1464.72,898.11 1464.72,1031.65 1484.25,1051.18 1529.58,1051.18 1535.43,1057.04 C71.2@1535.43,1094.49 ; L2.2@1474.88,768.7 1474.88,757.41 v1(1507.87,724.41)
COMHR_N: C76.1 R128.2 T1.3 | length 260.8
  Top Layer w10: v1(1295.28,1311.02) 1348.43,1257.87 T1.3@1348.43,1215.11 ; v1@1295.28,1314.96 R128.2@1295.28,1346.46
  Bottom Layer w10: v1(1295.28,1311.02) C76.1@1374.02,1232.28
COMHR_P: C71.1 R121.2 T1.1 | length 285.1
  Top Layer w10: v1(1484.25,1311.02) R121.2@1484.25,1346.46 ; v1@1484.76,1310.51 1549.21,1246.06 1559.1,1246.06 1564.96,1240.2 T1.1@1564.75,1215.11
  Bottom Layer w10: v1(1484.25,1311.02) 1562.99,1232.28 C71.1@1562.99,1228.35
COML_ISO_N: J9.1 L3.3 R140.2 | length 378.4
  Top Layer w10: J9.1@878.14,511.81 895.35,529.02 918.78,529.02 997.13,607.36 1012.87,607.36 R140.2@1015.75,610.24
  Bottom Layer w10: J9.1@878.14,511.81 895.35,529.02 918.78,529.02 997.56,607.8 L3.3@997.56,648.62
COML_ISO_P: J9.2 L3.4 R133.2 | length 427.4
  Top Layer w10: J9.2@778.14,511.81 876.57,610.24 R133.2@929.13,610.24
  Bottom Layer w10: J9.2@778.14,511.81 915.94,649.61 L3.4@956.69,649.61
COML_N: R137.1 U2.44 | length 479.6
  Top Layer w10: R137.1@1289.68,2366.14 1241.27,2366.14 1241.27,2370.08 1224.72,2386.63 1224.72,2412.98 1252.69,2440.94 1370.08,2440.94 1379.61,2450.47 1586.3,2450.47 U2.44@1586.61,2450.79
COML_P: R130.1 U2.43 | length 512.5
  Top Layer w10: R130.1@1140.07,2366.14 1188.47,2366.14 1188.47,2370.08 1204.72,2386.33 1204.72,2421.26 1244.41,2460.94 1361.79,2460.94 1371.32,2470.47 U2.43@1586.61,2470.47
COML_R1_N: C81.2 J8.4 R135.1 R136.1 R137.2 R138.1 | length 1036.1
  Top Layer w10: R135.1@1089.61,1543.31 R138.1@1149.61,1543.31 ; R136.1@1148.62,1665.35 1113.19,1700.79 1072.79,1700.79 1066.93,1706.65 1066.93,1792.91 J8.4@1159.84,1885.83 1119.84,1925.83 1119.84,2087.62 1228.66,2196.44 1228.66,2234.3 1234.52,2240.16 1274.11,2240.16 1279.97,2246.02 1279.97,2259.81 1286.78,2266.62 C81.2@1290.72,2266.62 ; R138.1@1149.61,1547.24 R136.1@1149.61,1661.42 ; R137.2@1289.68,2318.9 R137.2@1289.68,2311.02 1289.68,2269.38 C81.2@1291.34,2267.72
COML_R1_P: C78.1 J8.5 R130.2 R131.1 R134.2 R135.2 | length 1040.6
  Top Layer w10: R131.1@960.63,1543.31 R135.2@1026.62,1543.31 ; R131.1@960.63,1547.24 R134.2@960.63,1661.42 ; R134.2@961.61,1665.35 997.05,1700.79 1037.45,1700.79 1043.31,1706.65 1043.31,1797.58 1090.55,1844.82 1090.55,1854.33 1059.06,1885.83 J8.5@1059.84,1885.83 1099.84,1925.83 1099.84,2095.91 1208.66,2204.72 1208.66,2234.3 1202.8,2240.16 1156.68,2240.16 1150.82,2246.02 1150.82,2259.81 1144.01,2266.62 C78.1@1140.07,2266.62 ; C78.1@1140.07,2269.99 R130.2@1140.07,2311.02 R130.2@1140.07,2318.9
COML_R2_N: R138.2 R139.1 U7.1 | length 129.2
  Top Layer w10: U7.1@1094.49,1492.13 1114.17,1492.13 1122.05,1484.25 1149.61,1484.25 R139.1@1149.61,1413.39
COML_R2_P: R131.2 R132.1 U7.2 | length 127.6
  Top Layer w10: R132.1@960.63,1413.39 R131.2@960.63,1484.25 ; R131.2@960.63,1496.06 964.57,1492.13 U7.2@1015.75,1492.13
COMLC_N: C82.2 L3.2 R140.1 T2.6 | length 587.1
  Top Layer w10: R140.1@1025.51,698.74 R140.1@1011.81,685.04 1011.81,708.66 v1(1027.56,724.41) ; v1@1027.56,726.29 1049.12,726.29 T2.6@1076.38,770.18
  Bottom Layer w10: L3.2@996.13,768.86 994.84,757.12 v1(1027.56,724.41) ; L3.2@997.56,768.7 997.56,777.56 988.19,786.93 988.19,1027.6 1011.77,1051.18 1053.2,1051.18 1059.06,1057.04 1059.06,1090.55 C82.2@1066.93,1098.43
COMLC_P: C77.2 L3.1 R133.1 T2.4 | length 590.2
  Top Layer w10: T2.4@868.11,778.08 868.11,759.43 905.18,722.36 v1@927.24,722.36 ; v1(925.2,724.41) v1@927.24,722.36 ; R133.1@928.86,697.13 R133.1@940.94,685.04 940.94,708.66 v1@927.24,722.36
  Bottom Layer w10: C77.2@893.7,1086.9 893.7,1057.04 899.56,1051.18 940.94,1051.18 964.57,1027.56 964.57,789.43 952.69,777.56 L3.1@952.69,768.7 ; v1(925.2,724.41) 956.69,755.91 L3.1@956.69,768.7
COMLR_N: C82.1 R139.2 T2.1 | length 292.1
  Top Layer w10: T2.1@1084.65,1215.11 1084.65,1250 v1@1151.57,1316.93 ; v1@1149.61,1318.9 R139.2@1149.61,1350.39
  Bottom Layer w10: C82.1@1070.87,1212.6 1070.87,1232.28 v1(1149.61,1311.02)
COMLR_P: C77.1 R132.2 T2.3 | length 283.1
  Top Layer w10: T2.3@868.11,1240.06 885.83,1240.16 v1(956.69,1311.02) 956.69,1342.52 R132.2@960.63,1346.46
  Bottom Layer w10: C77.1@866.14,1220.47 v1(956.69,1311.02)
DCDC_SW: L10.1 U1.33 | length 96
  Top Layer w9.45: L10.1@2562.99,905.51 2582.68,885.83 2582.68,883.89 2587.83,878.74 2601.58,878.74 2604.33,875.98 U1.33@2645.67,875.98
DCOUPL_CC: C108.1 U1.23 | length 89.1
  Top Layer w9.45: C108.1@2657.48,1125.98 2657.48,1103.96 2663.02,1098.43 2677.17,1098.43 2690.94,1084.65 U1.23@2690.94,1059.06
DVDD: C14.1 S2.8 TP6.1 U2.41 | length 4145.5
  Top Layer w8: v1(1555.12,2035.43) 1606.3,1984.25 1673.23,1984.25 1744.09,1913.39 1905.51,1913.39 1964.57,1854.33 2460.63,1854.33 2614.17,2007.87 3111.12,2007.87 3277.03,1841.96 3538.82,1841.96 3649.61,1952.76 3649.61,2035.87 3649.61,2076.17 3663.79,2090.35 S2.8@3693.31,2090.35
  Top Layer w11.81: C14.1@1488.19,2496.06 v2(1523.62,2496.06) 1525.59,2496.06 1539.37,2509.84 U2.41@1586.61,2509.84
  Bottom Layer w11.81: TP6.1@578.74,2405.51 578.74,2384.25 620.47,2342.52 1370.08,2342.52 v2(1523.62,2496.06) 1523.62,2495.86 1535.43,2484.05 1535.43,2056.36 1555.12,2036.67 v1(1555.12,2035.43)
DVDD_LED: Q2.1 R26.2 S2.5 | length 2459
  Top Layer w10: S2.5@3393.31,2090.35 3393.5,2090.55 v2(3440.94,2090.55)
  Bottom Layer w8: v2(3440.94,2090.55) 3500,2149.61 3500,2279.53 3472.05,2307.48 3434.29,2307.48 3405.08,2336.68 3405.08,3066.5 3476.38,3137.8 3707.28,3137.8 3711.97,3142.48 3711.97,3952.92 R26.2@3743,3983.96 3771.36,3983.96 3818.9,4031.5 3818.9,4051.18 3828.74,4061.02 Q2.1@3856.3,4061.02
DVDD_LED_A: D2.2 R20.2 | length 74.8
  Top Layer w8: D2.2@3842.52,4122.05 v2(3874.02,4122.05)
  Bottom Layer w8: R20.2@3838.58,4122.05 v2@3881.89,4122.05
DVDD_LED_D: D2.1 Q2.3 | length 87.4
  Top Layer w8: v2(3779.53,4078.74) D2.1@3779.53,4122.05
  Bottom Layer w8: v2(3779.53,4078.74) 3781.5,4076.77 Q2.3@3781.5,4035.43
EN_LSF: R150.2 U13.8 | length 258.2
  Top Layer w10: R150.2@3376.13,1466.8 3399.87,1466.8 3425.09,1492.02 3495.96,1492.02 3496.06,1492.13 3562.99,1492.13 3576.77,1505.91 U13.8@3576.77,1547.24
F_LED_POL: Q1.1 Q3.3 R23.1 | length 349.6
  Bottom Layer w8: Q3.3@3781.5,3700.79 3781.5,3750 3830.71,3799.21 3830.71,3844.49 ; R23.1@3795.28,3956.69 3791.34,3956.69 3783.53,3948.88 3783.53,3944.94 3769.53,3930.94 3769.53,3889.56 3789.07,3870.02 3805.18,3870.02 3830.71,3844.49 ; Q1.1@3856.3,3844.49 3830.71,3844.49
FAULT_LED: Q3.1 R24.1 S1.4 | length 1405.7
  Top Layer w10: S1.4@3393.31,2927.76 3393.84,2927.22 v2(3430.35,2927.22)
  Bottom Layer w8: v2(3430.35,2927.22) 3430.35,3068.84 3475.68,3114.17 3723.66,3114.17 3728.35,3118.86 3728.35,3606.3 3818.9,3696.85 3818.9,3712.6 3832.49,3726.19 3856.11,3726.19 Q3.1@3856.3,3726.38 3875.98,3726.38 3881.89,3732.28 3881.89,3893.7 3870.08,3905.51 R24.1@3842.52,3905.51
FAULT_LED_A: D3.2 R21.1 | length 74.8
  Top Layer w8: D3.2@3842.52,4185.04 v2(3874.02,4185.04)
  Bottom Layer w8: R21.1@3838.58,4185.04 v2@3881.89,4185.04
FAULT_LED_D: D3.1 Q1.3 | length 422.2
  Top Layer w8: D3.1@3787.4,4185.04 3803.15,4185.04 3811.02,4177.17 3811.02,4066.93 3795.28,4051.18 3795.28,3854.33 3807.09,3842.52 v2(3807.09,3818.9)
  Bottom Layer w8: Q1.3@3781.5,3818.9 v2(3807.09,3818.9)
FAULT_WL: S1.3 U13.11 | length 1570.7
  Top Layer w8: v2(3389.74,1775.17) 3390.16,1775.59 3425.2,1775.59 3500,1700.79 U13.11@3500,1547.24
  Top Layer w10: v2(3342.1,2971.9) 3345.35,2971.9 3351.21,2977.76 S1.3@3393.31,2977.76
  Bottom Layer w8: v2(3342.1,2971.9) 3342.1,1813.09 3377.34,1777.85 3387.06,1777.85 v2(3389.74,1775.17)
